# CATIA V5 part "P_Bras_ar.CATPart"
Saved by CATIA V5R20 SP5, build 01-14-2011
Part number: Bras_ar
Bounding box of the stored display mesh (mm): x -4 to 4, y 132.727 to 192.727, z -9 to 150
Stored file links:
  U:\2A\CFAO\dossier sans titre\P_Bras_ar.CATPart
  U:\2A\CFAO\dossier sans titre\Gouvernail.CATProduct
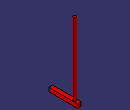
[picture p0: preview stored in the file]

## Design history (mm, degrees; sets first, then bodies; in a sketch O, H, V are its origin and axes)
External parameters (linked from other documents)
  External.Larg_Totale = 450 mm
Set1
  Point1 to Point3: linked copy from another document
Body1 (main body)
  Sketch1 on yz-plane, origin (0, 0, 0), H (0, 1, 0), V (0, 0, 1)
    line L1 (132.7273, -1) -> (192.7273, -1)
    line L2 (192.7273, -1) -> (192.7273, -9)
    line L3 (192.7273, -9) -> (132.7273, -9)
    line L4 (132.7273, -9) -> (132.7273, -1)
    reference projected point E1 (182.7273, 0) from Point1
    length L1 = 60 {= (60/450)*External.Larg_Totale}
    length L2 = 8
    distance L2 E1 = 10
    distance L1 H = 1
    horizontal: L1 H, L3 H
    vertical: L2 V, L4 V
  Pad1 "Extrusion_corps": profile Sketch1, direction (1, 0, 0), length 4, opposite side length 4
  Sketch2 on xy-plane, origin (0, 0, 0), H (1, 0, 0), V (0, 1, 0)
    circle A1 centre (0, 182.7273) radius 3
    point P1 (0, 182.7273)
    reference projected point E1 (0, 182.7273) from Point3
    radius A1 = 3
    coincidence: P1 E1
  Pad2 "Extrusion_axe": profile Sketch2, direction (0, 0, 1), length 150, opposite side length 2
